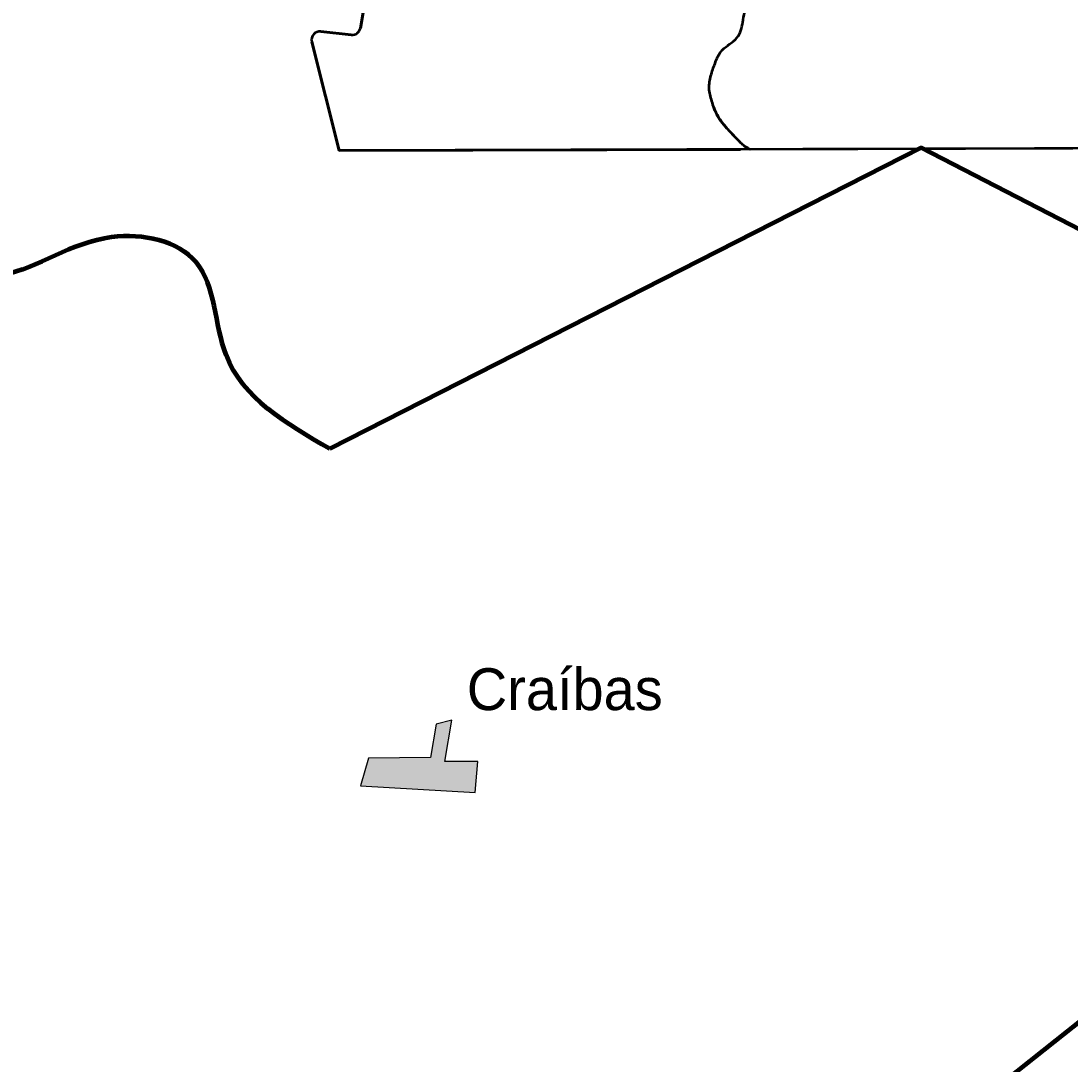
# Model space of a CAD drawing. Extents: x -1643653 to 4543381, y 1624270 to 13878484.
# Drawn here: x 740225 to 752758, y 8932691 to 8945147 of the extents above; entities that cross this region are included whole.
import ezdxf

# ---------------------------------------------------------------- set-up
doc = ezdxf.new("R2010")
doc.units = 0
doc.header["$LTSCALE"] = 200
for name, color, linetype, lineweight in [('21', 7, 'Continuous', 25), ('59', 7, 'Continuous', 53), ('60', 7, 'Continuous', 13), ('9', 7, 'Continuous', 90)]:
    doc.layers.add(name, color=color, linetype=linetype, lineweight=lineweight)
doc.layers.add('41', color=7, linetype='Continuous')

msp = doc.modelspace()

# ---------------------------------------------------------------- hatches: boundary and pattern name
at = {"layer": '21'}
msp.add_hatch(color=256, dxfattribs=at).paths.add_polyline_path([(745187, 8936748.8), (745117.1, 8936352.5), (744378.8, 8936344.3), (744279.6, 8936014.5), (745653.1, 8935932.8), (745681.3, 8936302.9), (745288.9, 8936302.6), (745373.5, 8936795.4)])

# ---------------------------------------------------------------- linework, layer by layer
msp.add_lwpolyline([(745187, 8936748.8), (745117.1, 8936352.5), (744378.8, 8936344.3), (744279.6, 8936014.5), (745653.1, 8935932.8), (745681.3, 8936302.9), (745288.9, 8936302.6), (745373.5, 8936795.4)], close=True, dxfattribs=at)
at = {"layer": '59'}
for p, q in [((744280.4, 8945063), (744377.1, 8945615.3)), ((744377.1, 8945615.3), (744280.4, 8945063)), ((743808.6, 8945021.6), (744170.7, 8944980.9)), ((744170.7, 8944980.9), (743808.6, 8945021.6))]:
    msp.add_line(p, q, dxfattribs=at)
for points in [[(758733.2, 8945259.8), (758673.7, 8944290.6), (757932.3, 8943725.4), (757924.1, 8943639.7), (748941.6, 8943614.3)], [(757873.8, 8943639.6), (744028.3, 8943600.4), (743700.5, 8944897.8)], [(743700.5, 8944897.8), (744028.3, 8943600.4), (748822.6, 8943613.9)]]:
    msp.add_lwpolyline(points, dxfattribs=at)
for centre, start, end in [((743797.4, 8944922.3), 83.57781, 194.1793), ((743797.4, 8944922.3), 83.57781, 194.1793), ((744181.9, 8945080.3), 263.57781, 350.06556), ((744181.9, 8945080.3), 263.57781, 350.06556)]:
    msp.add_arc(centre, 100, start, end, dxfattribs=at)
for points in [[(748941.6, 8943614.3), (748896.5, 8943634.1), (748856, 8943659.8), (748822.4, 8943694.2), (748676.6, 8943843.1), (748534.4, 8944006.2), (748476.8, 8944200.3), (748436.1, 8944337.6), (748464.7, 8944500.4), (748513.9, 8944632.3), (748581.4, 8944813.6), (748809.8, 8944932.5), (748847.1, 8945126.1), (748894.1, 8945370.7), (748803.2, 8945634.3), (748847.1, 8945879.1), (748911.7, 8946239.9), (749046.9, 8946596.2), (749112.4, 8946956.9), (749156.8, 8947201.7), (749082.3, 8947460.6), (749137.1, 8947709.9), (749185.9, 8947932.1), (749331.9, 8948116.3), (749532, 8948253), (749660.7, 8948341), (749841.6, 8948192), (749963.9, 8948265.4), (750406.1, 8948530.4), (750825.5, 8948830.5), (751225.2, 8949186.3), (751509.6, 8949439.5), (751808.2, 8949666.9), (752064, 8949931.3)], [(748822.4, 8943694.2), (748676.6, 8943843.1), (748534.4, 8944006.2), (748476.8, 8944200.3), (748436.1, 8944337.6), (748464.7, 8944500.4), (748513.9, 8944632.3), (748581.4, 8944813.6), (748809.8, 8944932.5), (748847.1, 8945126.1), (748894.1, 8945370.7), (748803.2, 8945634.3), (748847.1, 8945879.1), (748911.7, 8946239.9), (749046.9, 8946596.2), (749112.4, 8946956.9), (749156.8, 8947201.7), (749082.3, 8947460.6), (749137.1, 8947709.9), (749185.9, 8947932.1), (749331.9, 8948116.3), (749532, 8948253), (749660.7, 8948341), (749841.6, 8948192), (749963.9, 8948265.4), (750406.1, 8948530.4), (750825.5, 8948830.5), (751225.2, 8949186.3), (751509.6, 8949439.5), (751808.2, 8949666.9), (752064, 8949931.3)]]:
    msp.add_open_spline(points, degree=3, dxfattribs=at)
at = {"layer": '60', "lineweight": 25}
msp.add_spline([(814781, 9009175.5), (814787.2, 9009173.4), (814796.9, 9009173.4), (814799.4, 9009172.4), (814805.1, 9009174.5), (814805.6, 9009176.5), (814811.7, 9009179.5), (814811.7, 9009179.5), (814801.5, 9009181), (814790.7, 9009181.5), (814784.1, 9009183.1), (814777.4, 9009185.1), (814778.4, 9009175.5)], degree=3, dxfattribs=at)
at = {"layer": '9'}
msp.add_line((742465.8, 8924928.2), (760739.9, 8939450.1), dxfattribs=at)
for points in [[(760739.9, 8939450.1), (758705.7, 8940260.8), (758249.4, 8940131.7), (757970.6, 8940028.8), (750978.7, 8943631.9), (743914.7, 8940037.6)], [(760739.9, 8939450.1), (758705.7, 8940260.8), (758249.4, 8940131.7), (757970.6, 8940028.8), (750978.7, 8943631.9), (743914.7, 8940037.6)], [(760739.9, 8939450.1), (742465.8, 8924928.2), (740378.1, 8923196.1), (741055, 8921600.7)]]:
    msp.add_lwpolyline(points, dxfattribs=at)
for points in [[(743914.7, 8940037.6), (742675.2, 8941159), (742317.7, 8942267.2), (741308, 8942564.7), (740014, 8942114.2), (737849.4, 8942996.8)], [(743914.7, 8940037.6), (742675.2, 8941159), (742317.7, 8942267.2), (741308, 8942564.7), (740014, 8942114.2), (737849.6, 8942996.8)]]:
    msp.add_spline(points, degree=3, dxfattribs=at)

# ---------------------------------------------------------------- texts
at = {"layer": '41'}
msp.add_text('Craíbas', height=500, dxfattribs=at).set_placement((745551.3, 8936916.9))

doc.saveas('drawing.dxf')
